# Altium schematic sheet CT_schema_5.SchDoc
size 312 x 238 mm
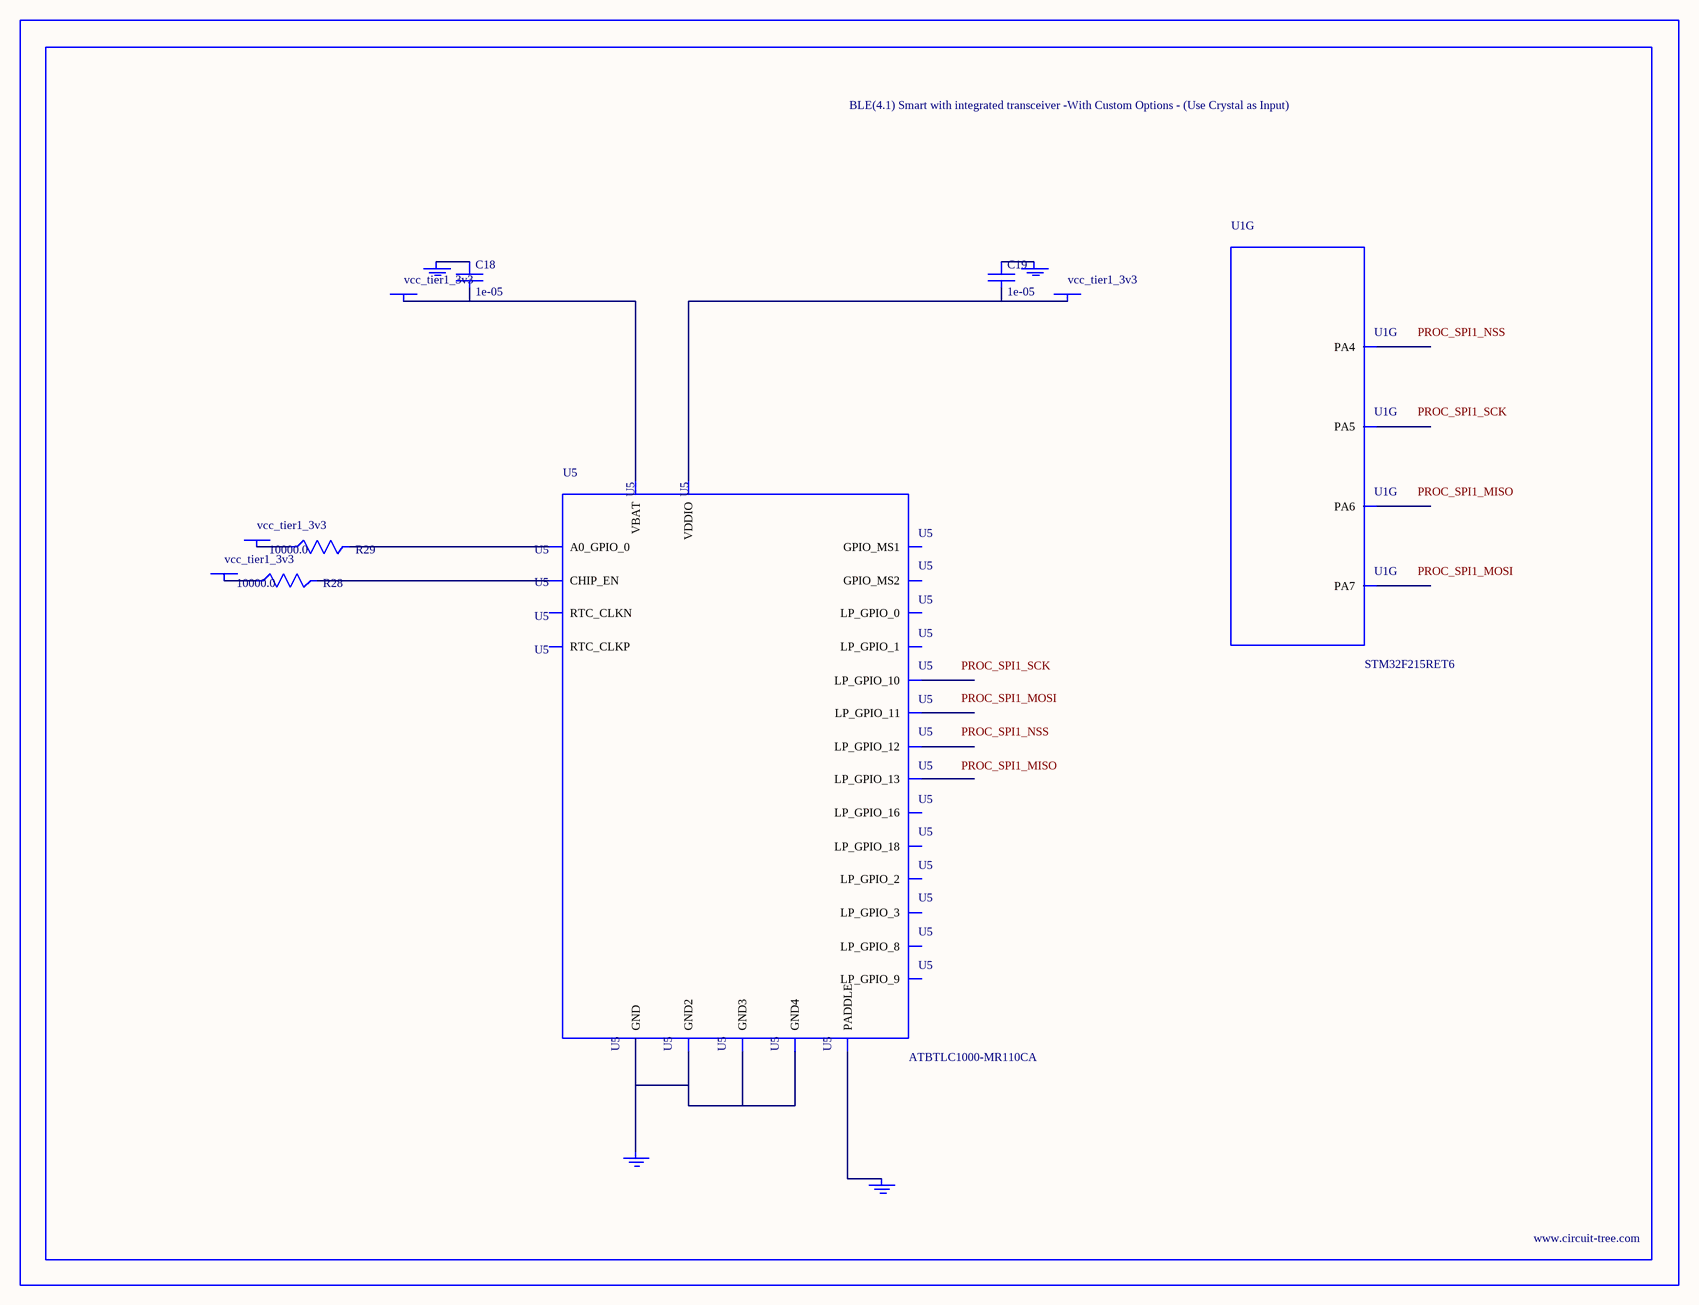
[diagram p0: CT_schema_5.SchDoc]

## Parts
BORDER4  (no value)
C18  1e-05  [C0805]
C19  1e-05  [C0805]
GND_INSTANCE_4_0  (no value)
GND_INSTANCE_4_1  (no value)
GND_INSTANCE_4_2  (no value)
GND_INSTANCE_4_3  (no value)
POWER_INSTANCE_4_0  vcc_tier1_3v3
POWER_INSTANCE_4_1  vcc_tier1_3v3
POWER_INSTANCE_4_2  vcc_tier1_3v3
POWER_INSTANCE_4_3  vcc_tier1_3v3
R28  10000.0  [R0603]
R29  10000.0  [R0603]
U1  STM32F215RET6  [LQFP64]  (part G of 7)
U5  ATBTLC1000-MR110CA  [ATBTLC1000-MR110CA]

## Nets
NetC18_1: C18.1 GND_INSTANCE_4_0.0(GND)
NetC18_2: C18.2 POWER_INSTANCE_4_0.0(PWR) U5.6(VBAT)
NetC19_1: C19.1 GND_INSTANCE_4_1.0(GND)
NetC19_2: C19.2 POWER_INSTANCE_4_3.0(PWR) U5.22(VDDIO)
NetGND_INSTANCE_4_2_0: GND_INSTANCE_4_2.0(GND) U5.25(PADDLE)
NetGND_INSTANCE_4_3_0: GND_INSTANCE_4_3.0(GND) U5.1(GND) U5.9(GND2) U5.13(GND3) U5.24(GND4)
NetPOWER_INSTANCE_4_1_0: POWER_INSTANCE_4_1.0(PWR) R28.1
NetPOWER_INSTANCE_4_2_0: POWER_INSTANCE_4_2.0(PWR) R29.1
NetR28_2: R28.2 U5.17(CHIP_EN)
NetR29_2: R29.2 U5.20(A0_GPIO_0)

Not connected (* = marked no-connect by the designer): U1 20(PA4) 21(PA5) 22(PA6) 23(PA7); U5 2(LP_GPIO_0) 3(LP_GPIO_1) 4(LP_GPIO_2) 5(LP_GPIO_3) 7(LP_GPIO_8) 8(LP_GPIO_9) 10(LP_GPIO_10) 11(LP_GPIO_11) 12(LP_GPIO_12) 14(LP_GPIO_13) 15(GPIO_MS1) 16(GPIO_MS2) 18(RTC_CLKP) 19(RTC_CLKN) 21(LP_GPIO_16) 23(LP_GPIO_18)

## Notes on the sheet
- Labels drawn without touching a wire or pin: PROC_SPI1_MISO, PROC_SPI1_MOSI, PROC_SPI1_NSS, PROC_SPI1_SCK

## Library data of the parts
BORDER4 = BORDER_PAGE4
C18 C19 = C0805C106K8RACTU
GND_INSTANCE_4_0-GND_INSTANCE_4_3 = GND
POWER_INSTANCE_4_0-POWER_INSTANCE_4_3 = PWR
R28 R29 = RC0603JR-0710KL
